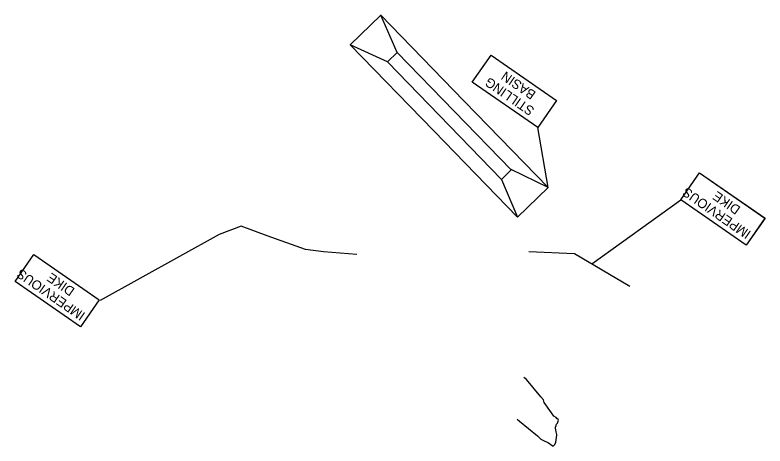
# Model space of a CAD drawing. Extents: x 476586 to 481096, y 489307 to 500930.
# Drawn here: x 478753.4 to 479230.7, y 493873.9 to 494148.5 of the extents above; entities that cross this region are included whole.
import ezdxf

# ---------------------------------------------------------------- set-up
doc = ezdxf.new("R2010")
doc.units = 0
for name, color, linetype in [('DTM Contours Minor', 7, 'Continuous'), ('Impervious Dike CG', 7, 'Continuous'), ('Impervious Dike Note CG CELL', 7, 'Continuous'), ('Prop Grid Mask', 7, 'Continuous'), ('Stilling Basin CG CELL', 7, 'Continuous')]:
    doc.layers.add(name, color=color, linetype=linetype)

msp = doc.modelspace()

# ---------------------------------------------------------------- linework, layer by layer
at = {"layer": 'DTM Contours Minor'}
msp.add_lwpolyline([(479073.05, 493890.95), (479074.54, 493889.84), (479085.98, 493880.39), (479088.1, 493878.31), (479089.36, 493877.65), (479092.95, 493876.02), (479095.94, 493873.94), (479097.06, 493874.85), (479097.51, 493876.35), (479098.24, 493880.93), (479098.25, 493881.23), (479097.86, 493882.97), (479097.38, 493885.33), (479097.38, 493886.14), (479097.55, 493886.46), (479098.07, 493887.89), (479098.75, 493888.5), (479099.33, 493890.42), (479099.06, 493890.74), (479098.21, 493891.5), (479097.74, 493892.01), (479096.39, 493892.87), (479094.83, 493895.08), (479090.16, 493901.59), (479089.67, 493903.32), (479087.99, 493905.27), (479078.88, 493916.21), (479077.3, 493917.56)], dxfattribs=at)
at = {"layer": 'Impervious Dike CG'}
for p, q in [((479080.39, 493997.77), (479109.52, 493996.53)), ((479109.52, 493996.53), (479144.72, 493975.78))]:
    msp.add_line(p, q, dxfattribs=at)
msp.add_lwpolyline([(478971.04, 493995.94), (478949.72, 493997.62), (478938.29, 493999.05), (478913.8, 494007.8), (478897.34, 494013.92), (478883.26, 494008.76)], dxfattribs=at)
at = {"layer": 'Impervious Dike Note CG CELL'}
for p, q in [((479092.64, 494038.59), (479086.09, 494076.74)), ((479120.46, 493990.08), (479177.11, 494030.73)), ((478883.26, 494008.76), (478807.64, 493966.66))]:
    msp.add_line(p, q, dxfattribs=at)
for points in [[(479086.11, 494076.76), (479044.45, 494105.66), (479056.4, 494122.88), (479098.05, 494093.98)], [(479218.77, 494001.83), (479177.11, 494030.73), (479189.06, 494047.95), (479230.71, 494019.05)], [(478795.06, 493949.88), (478753.4, 493978.77), (478765.34, 493996), (478807, 493967.09)]]:
    msp.add_lwpolyline(points, close=True, dxfattribs=at)
at = {"layer": 'Prop Grid Mask'}
for points in [[(479086.09, 494076.74), (479044.43, 494105.64), (479056.38, 494122.86), (479098.04, 494093.97)], [(479218.77, 494001.83), (479177.11, 494030.73), (479189.06, 494047.95), (479230.72, 494019.06)], [(478795.06, 493949.88), (478753.4, 493978.77), (478765.34, 493996), (478807, 493967.1)]]:
    msp.add_lwpolyline(points, close=True, dxfattribs=at)
at = {"layer": 'Stilling Basin CG CELL'}
for p, q in [((478966.8, 494129.54), (478986.12, 494148.41)), ((478986.07, 494148.49), (479039.32, 494093.56)), ((478996.7, 494124.66), (478986.12, 494148.41)), ((479020.02, 494074.65), (478966.8, 494129.54)), ((478990.37, 494118.56), (478966.8, 494129.54)), ((478990.45, 494118.58), (478996.7, 494124.66)), ((478996.7, 494124.66), (479069.16, 494049.91)), ((479062.92, 494043.77), (478990.45, 494118.58)), ((479039.32, 494093.56), (479092.64, 494038.59)), ((479073.25, 494019.78), (479020.02, 494074.65)), ((479069.16, 494049.91), (479062.92, 494043.77)), ((479092.64, 494038.59), (479069.15, 494049.97)), ((479062.92, 494043.77), (479073.25, 494019.78)), ((479092.64, 494038.59), (479073.25, 494019.78))]:
    msp.add_line(p, q, dxfattribs=at)

# ---------------------------------------------------------------- texts
at = {"layer": 'Impervious Dike Note CG CELL'}
for s, p in [('BASIN', (479085.38, 494099.16)), ('STILLING', (479084.48, 494088.83)), ('IMPERVIOUS', (479222.3, 494010.34)), ('DIKE', (479215.63, 494025.9)), ('IMPERVIOUS', (478798.58, 493958.38)), ('DIKE', (478791.91, 493973.95))]:
    msp.add_text(s, height=6, rotation=145.255, dxfattribs=at).set_placement(p)

doc.saveas('drawing.dxf')
